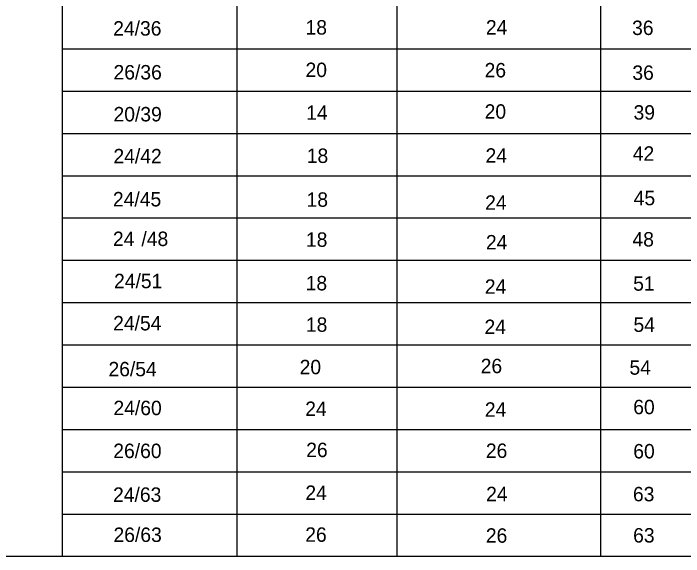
# Model space of a CAD drawing. Extents: x 635698 to 639877, y 296617 to 300175.
# Drawn here: x 638998.6 to 639138, y 299201.5 to 299314.6 of the extents above; entities that cross this region are included whole.
import ezdxf

# ---------------------------------------------------------------- set-up
doc = ezdxf.new("R2010")
doc.units = 0
doc.layers.add('1', color=7, linetype='Continuous')
doc.layers.add('3', color=7, linetype='Continuous')

msp = doc.modelspace()

# ---------------------------------------------------------------- linework, layer by layer
at = {"layer": '1'}
for p, q in [((639008.77, 299413.41), (639008.77, 299201.54)), ((639045.07, 299403.96), (639045.07, 299201.54)), ((639078.35, 299403.96), (639078.35, 299201.54)), ((639120.73, 299403.96), (639120.73, 299201.54)), ((639412.37, 299307.15), (639008.77, 299307.15)), ((639412.37, 299298.35), (639008.77, 299298.35)), ((639412.37, 299289.55), (639008.77, 299289.55)), ((639412.37, 299280.75), (639008.77, 299280.75)), ((639412.37, 299271.95), (639008.77, 299271.95)), ((639412.37, 299263.15), (639008.77, 299263.15)), ((639412.37, 299254.35), (639008.77, 299254.35)), ((639412.37, 299245.55), (639008.77, 299245.55)), ((639412.37, 299236.74), (639008.77, 299236.74)), ((639412.37, 299227.95), (639008.77, 299227.95)), ((639412.37, 299219.14), (639008.77, 299219.14)), ((639412.37, 299210.34), (639008.77, 299210.34)), ((639412.37, 299201.54), (638860.56, 299201.54))]:
    msp.add_line(p, q, dxfattribs=at)

# ---------------------------------------------------------------- texts
for s, p in [('26/54', (639018.39, 299239.07)), ('20', (639058.16, 299239.5)), ('26', (639095.82, 299239.72)), ('54', (639126.77, 299239.4))]:
    msp.add_text(s, height=2.998, dxfattribs=at).set_placement(p)
at = {"layer": '3'}
for s, height, p in [('24/36', 3.002, (639019.37, 299309.98)), ('18', 3.001, (639059.38, 299310.19)), ('24', 3.001, (639096.9, 299310.2)), ('36', 3.001, (639127.31, 299310.1)), ('26/36', 3.002, (639019.44, 299300.85)), ('20', 3.001, (639059.38, 299301.35)), ('26', 3.001, (639096.63, 299301.28)), ('36', 3.001, (639127.37, 299300.76)), ('20/39', 3.002, (639019.44, 299292.12)), ('14', 3.001, (639059.53, 299292.45)), ('20', 3.001, (639096.64, 299292.68)), ('39', 3.001, (639127.61, 299292.49)), ('24/42', 3.002, (639019.42, 299283.39)), ('18', 3.001, (639059.64, 299283.47)), ('24', 3.001, (639096.82, 299283.52)), ('42', 3.001, (639127.45, 299283.93)), ('24/45', 3.002, (639019.32, 299274.43)), ('18', 3.001, (639059.6, 299274.35)), ('24', 3.001, (639096.74, 299273.73)), ('45', 3.001, (639127.65, 299274.67)), ('24', 3.002, (639019.32, 299266.18)), ('/48', 3.002, (639025.24, 299266.18)), ('18', 3.001, (639059.47, 299266.02)), ('24', 3.001, (639096.91, 299265.47)), ('48', 3.001, (639127.39, 299266.09)), ('24/51', 3.002, (639019.55, 299257.4)), ('18', 3.001, (639059.41, 299256.95)), ('24', 3.001, (639096.68, 299256.24)), ('51', 3.001, (639127.54, 299256.88)), ('24/54', 3.002, (639019.36, 299248.62)), ('18', 3.001, (639059.46, 299248.33)), ('24', 3.001, (639096.61, 299247.86)), ('54', 3.001, (639127.6, 299248.31)), ('24/60', 3.002, (639019.42, 299230.98)), ('24', 3.001, (639059.32, 299230.82)), ('24', 3.001, (639096.68, 299230.65)), ('60', 3.001, (639127.55, 299231.18)), ('26/60', 3.002, (639019.39, 299222.05)), ('26', 3.001, (639059.52, 299222.25)), ('26', 3.001, (639096.89, 299222.08)), ('60', 3.001, (639127.56, 299221.98)), ('24/63', 3.002, (639019.34, 299212.94)), ('24', 3.001, (639059.35, 299213.34)), ('24', 3.001, (639096.95, 299213.07)), ('63', 3.001, (639127.49, 299213.05)), ('26/63', 3.002, (639019.43, 299204.59)), ('26', 3.001, (639059.32, 299204.62)), ('26', 3.001, (639096.89, 299204.43)), ('63', 3.001, (639127.53, 299204.47))]:
    msp.add_text(s, height=height, dxfattribs=at).set_placement(p)

doc.saveas('drawing.dxf')
